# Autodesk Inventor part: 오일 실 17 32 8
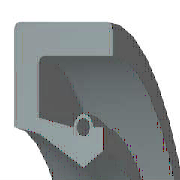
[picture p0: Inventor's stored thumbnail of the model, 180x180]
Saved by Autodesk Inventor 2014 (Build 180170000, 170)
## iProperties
IsCustomPart: 1
Created: 2012-02
Part Number: 오일 실 17 32 8
Material: 고무
Description: 오일-실
Document SubType Name: Modeling
Standard: KS B 2804
Designer: test
Standards Organization: KS
Language: ko-KR
Size Designation: S - 17 32 8
Categories: <MemberInstance><Categories><Category DisplayName="샤프트 부품" InternalName="7f7aeb1f-a693-4053-b835-cee3144e0d98" Mnemonic="SHFT"><Category DisplayName="실링" Intern
Density: 0.93 g/cm^3
Appearance: Rubber - Black - Version 1.1
Mass: 1.89534 g
Surface Area: 30.829 cm^2
Volume: 2.038 cm^3
Author: test
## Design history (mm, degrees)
revolve "본체" stored, may be unused: angle "d17" = 90 deg
revolve "스프링1" stored, may be unused: angle "d18" = 90 deg
body "Solid1"
sketch "스케치1"
  geometry: L1 (0, 16)-(8, 16); L2 (8, 16)-(8, 14.75); L3 (8, 14.75)-(1.75, 14.75); L4 (0, 16)-(0, 10.6); L5 (0, 10.6)-(1.75, 10.25); L6 (1.75, 10.25)-(4.9, 8.5); L7 (4.9, 8.5)-(0, 8.5); L8 (6.3, 9.375)-(6.3, 10.6); L9 (0, 0)-(9.586, 0) reference; L10 (4.9, 8.5)-(6.3, 9.375); L11 (0, 18)-(0, -3) reference; L12 (-1.917, 0)-(11.503, 0) reference; L13 (4.2, 10.6)-(1.75, 11.09); L14 (1.75, 11.09)-(1.75, 14.75); L15 (6.3, 10.6)-(5.6, 10.6); C1 r 0.455 at (4.9, 10.6); A1 r 0.7 centre (4.9, 10.6) between (5.6, 10.6) and (4.2, 10.6)
  constraints: 26 end point, 5 horizontal alignment, 4 perpendicular, 2 centre point, 2 collinear, 2 horizontal, 2 parallel, 2 point on circle, 2 point on line, 2 vertical alignment, 1 coincident
  dimensions: "d0" = 32 diameter of L1 L9 (= SD2); "d1" = 18.75 diameter of L8.start L9 (= ABDM); "d2" = 1.25 distance of L1.end L2.end (computed from SD); "d3" = 0.91 diameter of C1 (= SPDI); "d4" = 1.4 diameter of A1 (= SPDA); "d5" = 17 diameter of L6.end L9 (= NND); "d6" = 20.5 diameter of L5.end L9 (= TKDM); "d7" = 21.2 diameter of L4.end L9 (= HLDM); "d8" = 4.9 distance from line of C1.centre L4 (= SPDST); "d9" = 6.3 distance between parallel lines of L8 L4 (= SDI); "d10" = 8 distance between parallel lines of L2 L4 (= SWDT); "d12" = 1.75 distance between parallel lines of L14 L4 (= SD)
fillet "모깎기1" dims "d11" = 0.3 (= RR)
other parameters: "SD2" = 32 [user parameter; used in 1 equation term], "SWDT" = 8 [user parameter; used in 1 equation term], "RR" = 0.3 [user parameter; used in 1 equation term], "SD" = 1.75 [user parameter; used in 2 equation terms], "NND" = 17 [user parameter; used in 1 equation term], "SPDA" = 1.4 [user parameter; used in 1 equation term], "SPDI" = 0.91 [user parameter; used in 1 equation term], "TKDM" = 20.5 [user parameter; used in 1 equation term], "HLDM" = 21.2 [user parameter; used in 1 equation term], "ABDM" = 18.75 [user parameter; used in 1 equation term], "SDI" = 6.3 [user parameter; used in 1 equation term], "SPDST" = 4.9 [user parameter; used in 1 equation term], "d13" = 0, "d14" = 0, "d15" = 0, "LAB" = 0.35 [user parameter]
